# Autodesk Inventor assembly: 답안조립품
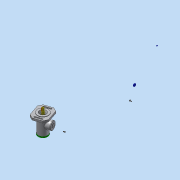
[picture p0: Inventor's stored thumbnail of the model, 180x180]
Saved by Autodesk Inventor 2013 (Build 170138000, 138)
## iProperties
Created: 2017-10
Part Number: 답안조립품
Document SubType Name: Assembly
Designer: Administrator
Author: Administrator
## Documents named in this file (20)
- C:\Users\Administrator\Desktop\471007V1004\답안조립품.iam
- C:\Users\Administrator\Desktop\471007V1004\V-벨트풀리.ipt
- C:\Users\Administrator\Desktop\471007V1004\너트 M10.ipt
- C:\Users\Administrator\Desktop\471007V1004\멈춤링 15 x 1.ipt
- C:\Users\Administrator\Desktop\471007V1004\멈춤링 35x1.6.ipt
- C:\Users\Administrator\Desktop\471007V1004\베어링 15 x 35 x 11.ipt
- C:\Users\Administrator\Desktop\471007V1004\본체.ipt
- C:\Users\Administrator\Desktop\471007V1004\볼트 M4 x 10.ipt
- C:\Users\Administrator\Desktop\471007V1004\부시1.ipt
- C:\Users\Administrator\Desktop\471007V1004\부시2.ipt
- C:\Users\Administrator\Desktop\471007V1004\사이드 커버.ipt
- 사이드 커버.ipt
- C:\Users\Administrator\Desktop\471007V1004\십자볼트 M3 x 10.ipt
- C:\Users\Administrator\Desktop\471007V1004\오일 실 15 25 7.ipt
- C:\Users\Administrator\Desktop\471007V1004\와셔 3x6.ipt
- C:\Users\Administrator\Desktop\471007V1004\와셔 4x16.ipt
- C:\Users\Administrator\Desktop\471007V1004\와셔 10x21.ipt
- C:\Users\Administrator\Desktop\471007V1004\축.ipt
- C:\Users\Administrator\Desktop\471007V1004\키 4 x 4 x 18.ipt
- C:\Users\Administrator\Desktop\471007V1004\탑 커버.ipt
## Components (2 placed, 2 different names)
1. V-벨트풀리:1
2. ISO 4017 M4 x 10:1
